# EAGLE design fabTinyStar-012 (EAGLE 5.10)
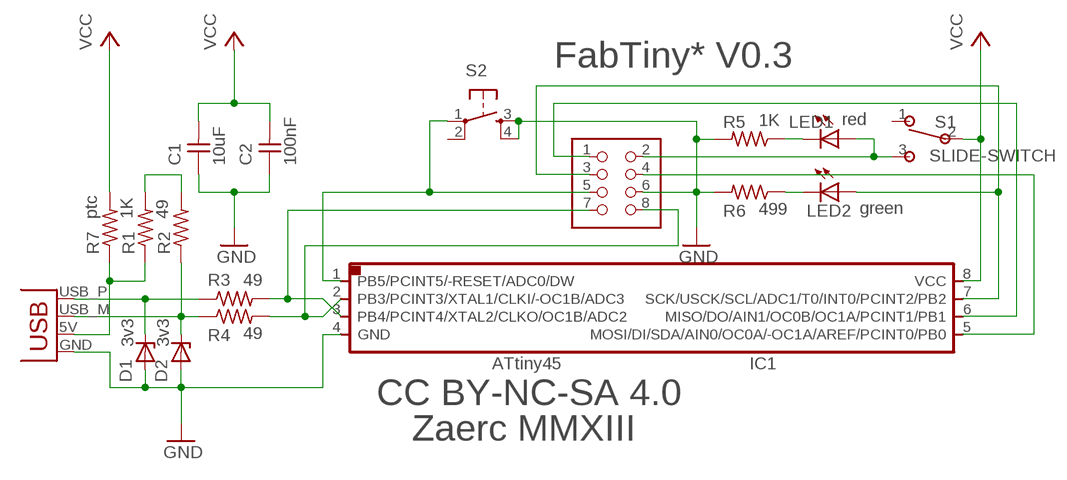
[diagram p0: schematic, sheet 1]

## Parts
C1  10uF  UNPOLARIZED_CAPACITOR1206  [1206]
C2  100nF  UNPOLARIZED_CAPACITOR1206  [1206]
D1  3v3  ZENER_DIODESOD123  [SOD123]
D2  3v3  ZENER_DIODESOD123  [SOD123]
IC1  ATTINY*5  ATTINY45SI  [SOIC8]
JP1  PINHD-2X04  [54202-G0808LF]
LED1  red  LEDSMT1206  [1206]
LED2  green  LEDSMT1206  [1206]
R1  1K  RESISTOR1206  [1206]
R2  49  RESISTOR1206  [1206]
R3  49  RESISTOR1206  [1206]
R4  49  RESISTOR1206  [1206]
R5  1K  RESISTOR1206  [1206]
R6  499  RESISTOR1206  [1206]
R7  ptc  RESISTOR1206  [1206]
S1  SLIDE-SWITCH  [AYZ0102AGRLC]
S2  6MM_SWITCH6MM_SWITCH  [6MM_SWITCH]
USB  USBPCB  [USB-A-PCB]

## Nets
5V: R1.1 R7.1 USB.5V(VBUS)
B0: IC1.5(MOSI/DI/SDA/AIN0/OC0A/-OC1A/AREF/PCINT0/PB0) JP1.4
B1: IC1.6(MISO/DO/AIN1/OC0B/OC1A/PCINT1/PB1) JP1.1
B2: IC1.7(SCK/USCK/SCL/ADC1/T0/INT0/PCINT2/PB2) JP1.3 LED2.A
B3: IC1.2(PB3/PCINT3/XTAL1/CLKI/-OC1B/ADC3) JP1.8 R4.2
B4: IC1.3(PB4/PCINT4/XTAL2/CLKO/OC1B/ADC2) JP1.7 R3.2
B5: IC1.1(PB5/PCINT5/-RESET/ADC0/DW) JP1.5 S2.1(P)
D+: D1.CATHODE R3.1 USB.USB_P(D+)
D-: D2.CATHODE R2.1 R4.1 USB.USB_M(D-)
GND: C1.1 C2.1 D1.ANODE D2.ANODE IC1.4(GND) JP1.6 R5.2 R6.2 S2.3(S) S2.4(S1) USB.GND
N$1: R1.2 R2.2
N$13: LED2.C R6.1
N$14: LED1.C R5.1
TP: JP1.2 LED1.A S1.3
VCC: C1.2 C2.2 IC1.8(VCC) R7.2 S1.2
Unconnected: S1.1 S2.2(P1)

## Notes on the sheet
- FabTiny* V0.3
- CC BY-NC-SA 4.0
- Zaerc MMXIII

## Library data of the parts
C1 C2 = 01_FAB_Hello:UNPOLARIZED_CAPACITOR: unpolarized_capacitor
D1 D2 = 01_fab:ZENER_DIODE: zener diode
IC1 = 01_fab:ATTINY45
JP1 = Zaerc:PINHD-2X04
LED1 LED2 = led:LED: LED
R1-R7 = 01_FAB_Hello:RESISTOR
S1 = Zaerc:SLIDE-SWITCH
S2 = 01_fab:6MM_SWITCH: OMRON SWITCH
USB = SparkFun:USB: USB Connectors USB-B-PTH is fully proven SKU : PRT-00139 USB-miniB is fully proven SKU : PRT-00587 USB-A-PCB is untested. USB-A-H is throughly reviewed, but untested. Spark Fun Electronics SKU : PRT-00437 USB-B-SMT is throughly reviewed, but untested. Needs silkscreen touching up. USB-A-S has not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

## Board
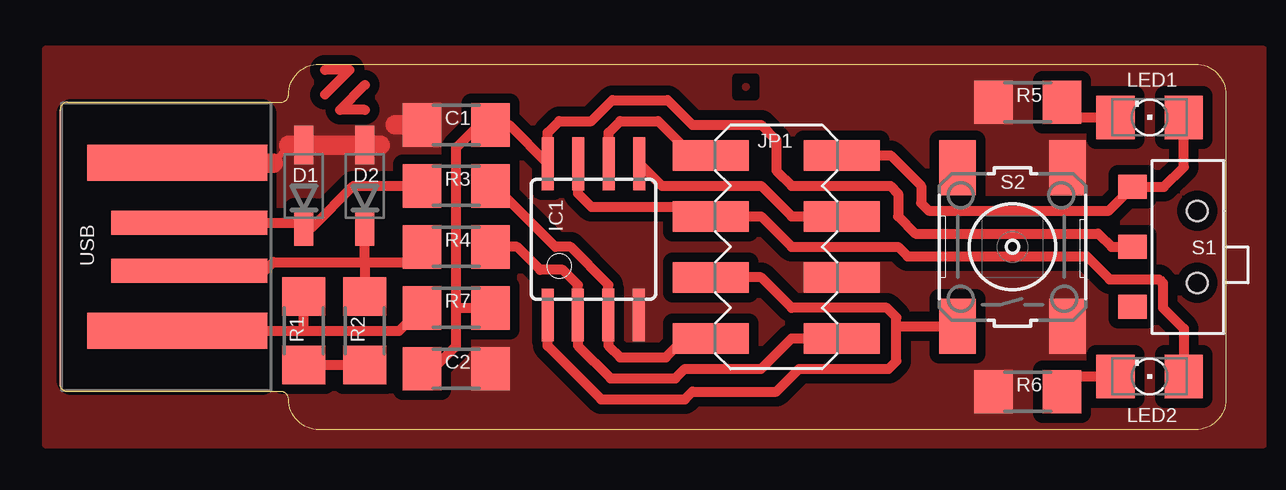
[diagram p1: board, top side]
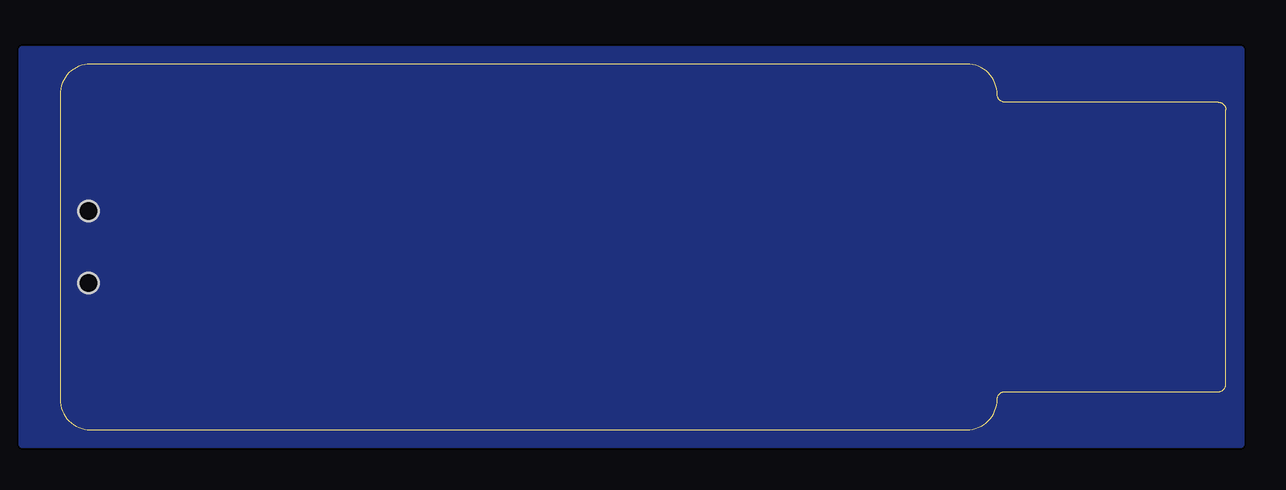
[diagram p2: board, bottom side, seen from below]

Size 48.58 x 15.24 mm. Coordinates in mm from the lower left corner, seen from the top.
Outline: 9.21,13.65 arc90 9.53,13.97 arc-90 10.79,15.24 47.31,15.24 arc-90 48.58,13.97 48.58,1.27 arc-90 47.31,0 10.79,0 arc-90 9.53,1.27 arc90 9.21,1.59 0.32,1.59 arc-90 0,1.91 0,13.34 arc-90 0.32,13.65 9.21,13.65
Copper layers (1*16): Top 0.035mm / dielectric 1.5mm / Bottom 0.035mm
Design rules "default *": minimum track width 10mil, minimum drill 24mil, track to track 16mil, track to pad 16mil, pad to pad 16mil, via to via 16mil, smd to smd 8mil, copper to edge 0mil, drill to drill 8mil, minimum pad ring 10mil, minimum via ring 8mil, stop-mask expansion 4mil, vias tented up to drill 0mil, thermal gap 10mil
tRestrict: area 0.5,2.1 to 8.4,13.2

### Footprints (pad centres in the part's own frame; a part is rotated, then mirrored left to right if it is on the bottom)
1206 = smd 1.6 x 1.803: 1 -1.422,0; 2 1.422,0
SOD123 = smd 1.6 x 0.8: ANODE 1.7,0; CATHODE -1.7,0
SOIC8 = smd 0.5 x 2.2: 1 -1.905,-3.154; 2 -0.645,-3.154; 3 0.625,-3.154; 4 1.895,-3.154; 5 1.905,3.154; 6 0.635,3.154; 7 -0.635,3.154; 8 -1.905,3.154
54202-G0808LF = smd 1.27 x 3.175: 1 -3.81,-2.731; 2 -3.81,2.731; 3 -1.27,-2.731; 4 -1.27,2.731; 5 1.27,-2.731; 6 1.27,2.731; 7 3.81,-2.731; 8 3.81,2.731
1206' = smd 1.6 x 1.803: A -1.422,0; C 1.422,0
AYZ0102AGRLC = smd 1 x 1.2: 1 2.5,-2.3; 2 0,-2.3; 3 -2.5,-2.3 | hole 0.85: -1.5,0.4; 1.5,0.4
6MM_SWITCH = smd 2.286 x 1.524: 1 -3.302,2.286; 2 3.302,2.286; 3 -3.302,-2.286; 4 3.302,-2.286
USB-A-PCB = smd 7.5 x 1.5: 5V -0.2,-3.5; GND -0.2,3.5 | smd 6.5 x 1: USB_M 0.3,-1; USB_P 0.3,1

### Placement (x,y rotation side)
C1  16.51,12.7 0 top
C2  16.51,2.54 180 top
D1  10.16,10.16 90 top
D2  12.7,10.16 90 top
IC1  22.23,7.94 0 top
JP1  29.84,7.62 270 top
LED1  red  [1206']  45.4,13.02 180 top
LED2  green  [1206']  45.4,2.22 180 top
R1  10.16,4.13 270 top
R2  12.7,4.13 270 top
R3  16.51,10.16 0 top
R4  16.51,7.62 0 top
R5  40.32,13.65 180 top
R6  40.32,1.59 180 top
R7  16.51,5.08 0 top
S1  46.99,7.62 270 top
S2  39.69,7.62 90 top
USB  5.08,7.62 0 top

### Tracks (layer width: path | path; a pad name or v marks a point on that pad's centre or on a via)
5V
  Top 0.406: USB.5V 10.16,4.12 | 10.16,4.12 14.13,4.12 R7.1 | 10.16,4.12 R1.1
B0
  Top 0.406: IC1.5 24.15,11.09 25.08,10.16 29.21,10.16 30.48,8.89 JP1.4
B1
  Top 0.406: IC1.6 22.86,12.38 23.34,12.86 24.92,12.86 26.35,11.43 JP1.1
B2
  Top 0.406: IC1.7 21.59,9.84 22.15,9.29 26.72,9.29 JP1.3 29.21,8.89 30.48,7.62 34.92,7.62 35.32,7.22 42.78,7.22 43.74,6.27 45.8,6.27 45.96,6.11 45.96,5.08 46.83,4.21 LED2.A
B3
  Top 0.406: R4.2 19.05,7.62 20,6.67 20.95,6.67 21.58,6.04 IC1.2 21.58,3.5 22.94,2.14 25.64,2.14 26.04,2.54 29.21,2.54 30.48,3.81 JP1.8
B4
  Top 0.406: R3.2 18.1,10.16 20.64,7.62 21.27,7.62 22.85,6.04 IC1.3 22.85,3.5 23.34,3.02 25.24,3.02 26.04,3.81 JP1.7
B5
  Top 0.406: IC1.1 20.32,3.49 22.54,1.27 26.04,1.27 26.35,1.59 29.84,1.59 30.8,2.54 34.53,2.54 34.85,2.86 34.85,4.29 | 34.85,4.29 34.85,4.68 34.45,5.08 30.48,5.08 29.21,6.35 JP1.5 | S2.1 34.88,4.32 34.85,4.29
D+
  Top 0.406: USB.USB_P 10,8.62 D1.CATHODE 10.52,8.46 12.22,10.16 R3.1
D-
  Top 0.406: USB.USB_M 8.53,6.62 8.89,6.99 12.7,6.99 | 12.7,6.99 R2.1 | 12.7,6.99 D2.CATHODE | 12.7,6.99 14.45,6.99 R4.1
GND
  Top 0.254: 8.89,11.11 9.53,11.86
  Top 0.813: 9.53,11.86 D1.ANODE D2.ANODE 13.34,11.86 | 8.89,11.11 USB.GND | C1.1 13.97,12.7
  pour Top (isolate 0.406, rank 6, no thermals): -0.64,-0.64 50.16,-0.64 50.16,15.88 -0.64,15.88
N$1
  Top 0.406: R1.2 R2.2
N$2
  pour Bottom: -0.64,-0.64 50.16,-0.64 50.16,15.88 -0.64,15.88
N$3
  pour Top: 28.57,14.13 28.58,14.13 arc90 28.73,14.29 arc90 28.57,14.45 arc90 28.42,14.29 28.42,14.29 arc90
N$13
  Top 0.406: LED2.C 42.38,2.22 R6.1
N$14
  Top 0.406: LED1.C 42.38,13.02 R5.1
N$33
  Top 0.406: 11.03,15 12.06,15 11.03,13.97
N$34
  Top 0.406: 12.7,14.37 11.67,13.34 12.7,13.34
TP
  Top 0.406: JP1.2 34.61,11.43 35.88,10.16 35.88,9.45 36.2,9.13 43.7,9.13 S1.3 46,10.12 46.83,10.95 LED1.A
VCC
  Top 0.406: C2.2 15.56,2.54 16.51,3.49 16.51,5.08 | 16.51,5.08 16.51,11.75 17.46,12.7 C1.2 18.71,12.7 IC1.8 20.32,12.38 20.8,12.86 22.15,12.86 23.02,13.73 25.32,13.73 26.35,12.7 29.21,12.7 29.84,12.06 29.84,10.79 30.48,10.16 34.61,10.16 34.92,9.84 34.92,8.89 35.64,8.18 43.26,8.18 43.81,7.62 S1.2 | 16.51,5.08 R7.2

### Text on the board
tDocu: FabTiny* v0.3 | CC BY-NC-SA 4.0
